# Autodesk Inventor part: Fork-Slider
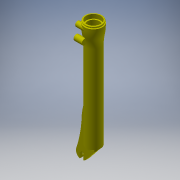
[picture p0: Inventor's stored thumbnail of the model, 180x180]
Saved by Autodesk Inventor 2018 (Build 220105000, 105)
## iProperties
Shininess: 11.0
Length Units: 11272
Angle Units: 11279
Time Units: 11290
Mass Units: 11286
Length Display Precision: 3
Angle Display Precision: 2
Compacted: True
Created: 2001-11
Part Number: Fork-Slider
Document SubType Name: Modeling
Designer: Autodesk, Inc.
Mass: 115.049 g
Surface Area: 625.889 cm^2
Volume: 115.049 cm^3
Density: 1 g/cm^3
Material: Generic
Appearance: Yellow (Flat)
Density: 0.0
Volumn: 0.0
Area: 0.0
PropertySet Name: Model Information
Control State: 0
Master: False
Checked Out: False
Author: Autodesk, Inc.
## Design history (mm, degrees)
node "WorkPlane1"
node "WorkPlane2"
workplane "Work Plane3"
node "WorkPlane3"
sketch "Sketch1"
  geometry: L1 (-491.904, 893.583)-(-489.986, 893.583); L2 (-491.94, 890.889)-(-492.507, 891.195); L3 (-493.987, 888.502)-(-492.544, 888.502); L4 (-493.987, 883.604)-(-493.987, 888.502); L5 (-491.593, 861.235)-(-492.38, 865.605); L6 (-489.986, 628.153)-(-489.986, 843.237); L7 (-477.096, 614.183)-(-489.986, 628.153); L8 (-475.254, 614.183)-(-477.096, 614.183); L9 (-475.254, 630.693)-(-475.254, 614.183); L10 (-486.875, 630.693)-(-475.254, 630.693); L11 (-486.875, 883.423)-(-486.875, 630.693); L12 (-489.986, 883.423)-(-486.875, 883.423); L13 (-489.986, 893.583)-(-489.986, 883.423); L14 (-472.221, 864.964)-(-472.221, 656.569); L15 (-472.221, 864.964)-(-472.221, 656.569); A1 r 1.27 centre (-491.904, 892.313) between (-491.904, 893.583) and (-492.507, 891.195); A2 r 1.27 centre (-492.544, 889.772) between (-492.544, 888.502) and (-491.94, 890.889); A3 r 101.6 centre (-392.387, 883.604) between (-493.987, 883.604) and (-492.38, 865.605); A4 r 101.6 centre (-591.586, 843.237) between (-489.986, 843.237) and (-491.593, 861.235)
  constraints: 30 end point, 8 point on circle, 7 tangent, 6 vertical, 5 horizontal, 4 centre point, 1 collinear, 1 other
revolve "RevolutionFull1" sketch "Sketch1" stored, may be unused: angle "d2" = 360 deg
sketch "Sketch2"
  geometry: L1 (-468.069, 628.153)-(-489.986, 628.153); L2 (-468.069, 735.894)-(-468.069, 628.153); L3 (-450.045, 605.991)-(-450.045, 592.726); L4 (-458.808, 592.726)-(-458.808, 605.991); L5 (-467.317, 599.747)-(-465.345, 597.277); L6 (-489.986, 628.153)-(-467.317, 599.747); A1 r 136.444 centre (-590.87, 676.421) between (-454.426, 676.794) and (-468.069, 735.894); A2 r 273.047 centre (-182.07, 696.209) between (-454.426, 676.794) and (-440.731, 608.748); A3 r 13.97 centre (-454.426, 605.991) between (-450.045, 592.726) and (-440.731, 608.748); A4 r 4.382 centre (-454.426, 605.991) between (-450.045, 605.991) and (-458.808, 605.991); A5 r 13.97 centre (-454.426, 605.991) between (-465.345, 597.277) and (-458.808, 592.726)
  constraints: 12 end point, 10 point on circle, 5 centre point
extrude "ExtrusionBlind1" join sketch "Sketch2" distance "d3" = 9.652; taper "d4" = 0 deg
node "WorkAxis1"
workplane "Work Plane5"
workplane "Work Plane6"
node "WorkPlane4"
workplane "Work Plane8"
node "WorkPlane5"
sketch "Sketch3"
  geometry: L1 (0, -4.165)-(0, 0); L2 (9.652, -4.076)-(9.652, -4.165); L3 (0, -4.165)-(9.652, -4.165); A1 r 17.766 centre (11.43, 13.6) between (0, 0) and (9.652, -4.076)
  constraints: 6 end point, 2 point on circle, 1 centre point
extrude "ExtrusionThru1" cut sketch "Sketch3" extent not by distance; stored distance "d17" = 3.302; taper "d18" = 0 deg
sketch "Sketch4"
  geometry: C1 r 14.654 at (14.546, 1.778)
  constraints: 1 centre point
extrude "ExtrusionThru2" cut sketch "Sketch4" extent not by distance; stored distance "d19" = 3.302; taper "d20" = 0 deg
sketch "Sketch5"
  geometry: L1 (-458.808, 605.991)-(-458.808, 592.726) reference; L2 (-450.045, 592.726)-(-450.045, 605.991) reference; A1 r 4.382 centre (-454.426, 605.991) between (-450.045, 605.991) and (-458.808, 605.991) reference; A2 r 10.668 centre (-454.426, 605.991) between (-450.045, 596.265) and (-458.808, 596.265)
  constraints: 2 point on circle, 2 point on line, 1 centre point
extrude "ExtrusionBlind2" cut sketch "Sketch5" distance "d21" = 4.572; taper "d22" = 0 deg
sketch "Sketch6"
  geometry: C1 r 6.985 at (-100.202, 21.766)
  constraints: 1 centre point
extrude "ExtrusionBlind3" join sketch "Sketch6" distance "d23" = 20.32; taper "d24" = 0 deg
node "Sketch7"
sketch "Sketch8"
  geometry: L1 (-126.546, 21.766)-(-131.444, 21.766) reference; L2 (-106.924, 19.867)-(-104.178, 19.373) reference; L3 (-108.547, 20.159)-(-106.924, 19.867) reference; L4 (-131.444, 21.766)-(-126.546, 21.766) reference; L5 (-131.444, 20.323)-(-131.444, 21.766) reference; L6 (-134.137, 20.286)-(-133.831, 19.719) reference; L7 (-136.525, 17.766)-(-136.525, 19.683) reference; L8 (-126.365, 17.766)-(-136.525, 17.766) reference; L9 (-126.365, 14.654)-(-126.365, 17.766) reference; L10 (126.365, 14.654)-(-126.365, 14.654) reference; L11 (126.365, 1.587)-(126.365, 14.654) reference; L12 (135.255, 1.587)-(126.365, 1.587) reference; L13 (135.255, 3.034)-(135.255, 1.587) reference; L14 (151.166, 3.034)-(135.255, 3.034) reference; L15 (151.166, 11.43)-(151.166, 3.034) reference; L16 (135.771, 11.43)-(151.166, 11.43) reference; L17 (128.905, 17.766)-(135.771, 11.43) reference; L18 (-86.179, 17.766)-(128.905, 17.766) reference; L19 (-104.178, -19.373)-(-108.547, -20.159) reference; L20 (-126.546, -21.766)-(-131.444, -21.766) reference; L21 (-131.444, -21.766)-(-131.444, -20.323) reference; L22 (-133.831, -19.719)-(-134.137, -20.286) reference; L23 (-136.525, -19.683)-(-136.525, -17.766) reference; L24 (-136.525, -17.766)-(-126.365, -17.766) reference; L25 (-126.365, -17.766)-(-126.365, -14.654) reference; L26 (-126.365, -14.654)-(126.365, -14.654) reference; L27 (126.365, -14.654)-(126.365, -1.587) reference; L28 (126.365, -1.587)-(135.255, -1.587) reference; L29 (135.255, -1.587)-(135.255, -3.034) reference; L30 (135.255, -3.034)-(142.875, -3.034) reference; L31 (142.875, -3.034)-(142.875, -4.875) reference; L32 (142.875, -4.875)-(128.905, -17.766) reference; L33 (128.905, -17.766)-(-86.179, -17.766) reference; C1 r 6.35 at (-124.333, 15.39); A1 r 6.985 centre (-100.202, 21.766) between (-94.264, 18.088) and (-106.924, 19.867) reference; A2 r 101.6 centre (-86.179, 119.366) between (-104.178, 19.373) and (-94.264, 18.088) reference; A3 r 101.6 centre (-126.546, -79.834) between (-108.547, 20.159) and (-123.263, 21.713) reference; A4 r 101.6 centre (-126.546, -79.834) between (-125.109, 21.756) and (-126.546, 21.766) reference; A5 r 1.27 centre (-132.714, 20.323) between (-133.831, 19.719) and (-131.444, 20.323) reference; A6 r 1.27 centre (-135.255, 19.683) between (-134.137, 20.286) and (-136.525, 19.683) reference; A7 r 101.6 centre (-86.179, 119.366) between (-94.264, 18.088) and (-86.179, 17.766) reference; A8 r 101.6 centre (-126.546, -79.834) between (-123.263, 21.713) and (-125.109, 21.756) reference; A9 r 101.6 centre (-86.179, -119.366) between (-86.179, -17.766) and (-104.178, -19.373) reference; A10 r 101.6 centre (-126.546, 79.834) between (-126.546, -21.766) and (-108.547, -20.159) reference; A11 r 1.27 centre (-132.714, -20.323) between (-131.444, -20.323) and (-133.831, -19.719) reference; A12 r 1.27 centre (-135.255, -19.683) between (-136.525, -19.683) and (-134.137, -20.286) reference
  constraints: 1 centre point, 1 tangent
extrude "ExtrusionBlind4" join sketch "Sketch8" distance "d26" = 23.368; taper "d27" = 0 deg
node "Sketch9"
extrude "ExtrusionToPlane1" cut stored distance "d29" = 3.302; taper "d30" = 0 deg
  node "Sketch10"
extrude "ExtrusionBlind5" cut distance "d31" = 50.8; taper "d32" = 0 deg
  node "Sketch11"
workplane "Work Plane10"
sketch "Sketch13"
  geometry: C1 r 3.034 at (0, 0); A1 r 3.034 centre (0, 0) between (-2.458, 1.778) and (2.458, 1.778) reference
  constraints: 1 centre point, 1 coincident, 1 concentric
workplane "Work Plane11"
extrude "Extrusion9" join sketch "Sketch13" stored distance "d34" = 25.4; taper "d35" = 0 deg
sketch "Sketch14"
  geometry: L1 (-2.458, 1.778)-(2.458, 1.778) reference; C1 r 3.034 at (0, 0); A1 r 3.034 centre (0, 0) between (-2.458, 1.778) and (2.458, 1.778) reference
  constraints: 1 centre point, 1 coincident, 1 concentric
extrude "Extrusion10" cut sketch "Sketch14" extent not by distance; stored distance "d36" = 25.4; taper "d37" = 0 deg
sketch "Sketch15"
  geometry: C1 r 3.034 at (0, 0) reference
hole "Hole1" sketch "Sketch15" at (0, 0) diameter "d38" = 3.175; stored, may be unused: countersink angle "d42" = 82 deg, drill point angle "d44" = 118 deg; dims "d39" = 12.7, "d40" = 9.525, "d41" = 6.35, "d43" = 19.05
sketch "Sketch16"
  geometry: C1 r 6.985 at (0, 0) reference
hole "Hole2" sketch "Sketch16" at (0, 0) diameter "d45" = 4.3434; stored, may be unused: countersink angle "d49" = 82 deg, drill point angle "d51" = 118 deg; dims "d46" = 12.7, "d47" = 9.525, "d48" = 6.35, "d50" = 12.7
sketch "Sketch17"
  geometry: C1 r 6.35 at (0, 0) reference
hole "Hole3" sketch "Sketch17" at (0, 0) diameter "d52" = 3.2512; stored, may be unused: countersink angle "d56" = 82 deg, drill point angle "d58" = 118 deg; dims "d53" = 12.7, "d54" = 9.525, "d55" = 6.35, "d57" = 12.7
body "Solid1"
other parameters: "d0" = -11.43, "d1" = -19.05, "d5" = 0, "d6" = 0, "d7" = 0, "d8" = 0, "d9" = 0, "d10" = 0, "d11" = 0, "d12" = 0, "d13" = 0, "d14" = 0, "d15" = 0, "d16" = 0, "d25" = 0, "d28" = 0, "d33" = -7.62
